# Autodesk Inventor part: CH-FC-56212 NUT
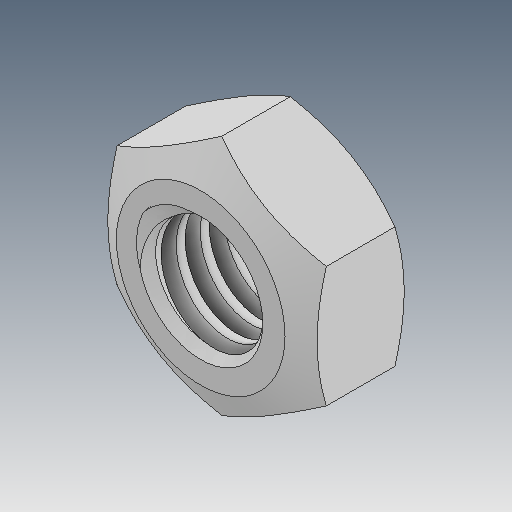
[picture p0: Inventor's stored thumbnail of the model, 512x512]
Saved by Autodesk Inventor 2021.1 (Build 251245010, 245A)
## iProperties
Created: 2020-03
Part Number: CH-FC-56212 NUT
Material: Ogólny
Document SubType Name: Modeling
Designer: user
Density: 1 g/cm^3
Appearance: Domyślna
Author: user
Revision Number: ÈÎºÎ
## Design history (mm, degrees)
feature "¾µÏò1"
node "Bryła1"
